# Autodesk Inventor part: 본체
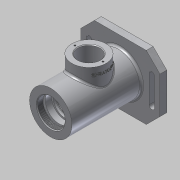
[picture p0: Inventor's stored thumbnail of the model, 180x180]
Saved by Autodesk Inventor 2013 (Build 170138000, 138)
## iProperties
Created: 2017-10
Part Number: 본체
Material: 알루미늄 6061
Document SubType Name: Modeling
Designer: Administrator
Density: 2.71 g/cm^3
Mass: 739.833 g
Surface Area: 655.925 cm^2
Volume: 273.001 cm^3
Author: Administrator
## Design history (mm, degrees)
sketch "스케치1"
  geometry: L1 (-58, 47)-(58, 47); L2 (58, 47)-(58, -47); L3 (58, -47)-(-58, -47); L4 (-58, -47)-(-58, 47); L5 (-58, 47)-(58, -47); L6 (58, 47)-(-58, -47); 1 further point
  constraints: 12 end point, 2 midpoint, 2 parallel, 1 horizontal, 1 perpendicular
  dimensions: "d3" = 116 distance of L2.end L3.end; "d4" = 94 distance of L1.end L2.end
extrude "돌출1" new body sketch "스케치1" distance "d5" = 10; taper "d6" = 0 deg
chamfer "모따기1" distance "d7" = 20; stored, may be unused: second distance "d8" = 2, angle "d9" = 45 deg
sketch "스케치2"
  geometry: L1 (31, 112)-(31, 10); L2 (27, 10)-(-27, 10) reference; L3 (0, 0)-(0, 188.497); L4 (-27, 0)-(27, 0) reference; L5 (47, 0)-(27, 0) reference; L6 (31, 112)-(21, 112); L7 (21, 112)-(21, 103); L8 (21, 103)-(24, 103); L9 (24, 103)-(24, 100); L10 (24, 100)-(20, 100); L11 (20, 100)-(20, 91); L12 (20, 91)-(17.5, 91); L13 (17.5, 91)-(17.5, 87.75); L14 (17.5, 87.75)-(18.5, 87.75); L15 (18.5, 87.75)-(18.5, 86); L16 (18.5, 86)-(17.5, 86); L17 (17.5, 86)-(17.5, 75); L18 (17.5, 75)-(26, 75); L19 (26, 75)-(26, 37); L20 (26, 37)-(17.5, 37); L21 (17.5, 37)-(17.5, 26.3); L22 (17.2, 26)-(16.5, 26); L23 (16.5, 26)-(16.5, 21); L24 (16.5, 21)-(10, 21); L25 (10, 21)-(10, 18.3); L26 (10, 18.3)-(12.2, 18.3); L27 (12.5, 18)-(12.5, 11.7); L28 (12.904, 11)-(16, 11); L29 (35, 0)-(35, -3); L30 (35, -3)-(0, -3); L31 (0, 0)-(0, -8.369); L32 (16, 11)-(22, -3); L33 (12.5, 11.7)-(12.904, 11); L34 (21, 112)-(0, 112); L35 (-47, 0)-(-47, 10) reference; L36 (-47, 10)-(47, 10) reference; L37 (47, 10)-(47, 0) reference; L38 (47, 0)-(-47, 0) reference; L39 (35, 0)-(31, 10); L40 (21, 103)-(0, 103); A1 r 0.3 centre (12.2, 18) between (12.5, 18) and (12.2, 18.3); A2 r 0.3 centre (17.2, 26.3) between (17.2, 26) and (17.5, 26.3)
  constraints: 66 end point, 23 parallel, 8 perpendicular, 6 point on line, 4 point on circle, 4 tangent, 2 centre point, 1 equal radius
  dimensions: "d10" = 62 diameter of L1 L3; "d14" = 42 diameter of L7 L3; "d15" = 48 diameter of L9 L3; "d16" = 40 diameter of L11 L3; "d17" = 35 diameter of L13 L3; "d18" = 37 diameter of L15 L3; "d19" = 35 diameter of L17 L3; "d20" = 52 diameter of L19 L3; "d21" = 35 diameter of L21 L3; "d22" = 33 diameter of L23 L3; "d23" = 20 diameter of L25 L3; "d24" = 25 diameter of L27 L3; "d25" = 32 diameter of L28.end L3; "d26" = 115 distance between parallel lines of L30 L6; "d27" = 44 diameter of L32.end L31; "d28" = 70 diameter of L29 L31; "d29" = 3 distance of L8.end L9.end; "d31" = 12 distance between parallel lines of L10 L6; "d32" = 21 distance between parallel lines of L12 L6; "d33" = 3 distance of L29.start L29.end; "d34" = 1.75 distance of L14.end L15.end; "d35" = 26 distance between parallel lines of L6 L16; "d36" = 11 distance of L16.end L17.end; "d37" = 38 distance of L18.end L19.end; "d38" = 14 distance between parallel lines of L30 L28; "d39" = 60 distance between parallel lines of L22 L16; "d40" = 5 distance of L22.end L23.end; "d42" = 2.7 distance of L24.end L25.end; "d43" = 30 deg angle of L27 L33; "d44" = 0.7 vertical distance of L28.start L27.end; "d45" = 0.3 radius of A1
  node "절단 모서리 투영1"
revolve "회전1" stored, may be unused: angle "d46" = 90 deg
revolve "회전2" stored, may be unused: angle "d47" = 90 deg
fillet "모깎기1" dims "d48" = 3
chamfer "모따기2" distance "d49" = 1; stored, may be unused: second distance "d50" = 2, angle "d51" = 45 deg
fillet "모깎기2" dims "d52" = 3
fillet "모깎기3" dims "d53" = 3
node "작업 평면1"
sketch "스케치3"
  geometry: L1 (38, 0)-(-38, 0) reference; L2 (-31, 112)-(31, 112) reference; C1 r 25 at (0, 56); 2 further points
  constraints: 1 centre point, 1 midpoint, 1 vertical alignment
  dimensions: "d55" = 56 distance from line of L2 C1.centre; "d56" = 50 diameter of C1
extrude "돌출2" join sketch "스케치3" stored distance "d57" = 10; taper "d58" = 0 deg
sketch "스케치4"
  geometry: C1 r 25 at (0, 0) reference; C2 r 16 at (0, 0); 1 further point
  constraints: 1 centre point, 1 coincident
  dimensions: "d59" = 32 diameter of C2
extrude "돌출3" cut sketch "스케치4" stored distance "d60" = 10; taper "d61" = 0 deg
chamfer "모따기4" distance "d65" = 1; stored, may be unused: second distance "d66" = 2, angle "d67" = 45 deg
fillet "모깎기4" dims "d68" = 3
sketch "스케치5"
  geometry: C1 r 25 at (0, 0) reference; C2 r 17 at (0, 0) reference; A1 r 20.5 centre (0, 0) between (-20.5, 0) and (20.5, 0); 1 further point
  constraints: 2 horizontal alignment, 2 point on circle, 1 centre point, 1 coincident
  dimensions: "d69" = 41 diameter of A1
hole "구멍1" sketch "스케치5" at (-20.5, 0), (20.5, 0) diameter "d70" = 2.459; stored, may be unused: countersink angle "d74" = 90 deg, drill point angle "d76" = 118 deg; dims "d71" = 6, "d72" = 4, "d73" = 2, "d75" = 8
sketch "스케치6"
  geometry: L1 (-42, 20)-(-42, -20); L2 (-50, 20)-(-50, -20); L3 (-38, 47)-(38, 47) reference; L4 (0, 0)-(0, 31); L5 (42, 20)-(42, -20); L6 (50, 20)-(50, -20); A1 r 4 centre (-46, 20) between (-42, 20) and (-50, 20); A2 r 4 centre (-46, -20) between (-50, -20) and (-42, -20); A3 r 4 centre (46, -20) between (42, -20) and (50, -20); A4 r 4 centre (46, 20) between (50, 20) and (42, 20)
  constraints: 10 end point, 8 point on circle, 6 symmetric about line, 4 centre point, 4 tangent, 1 equal radius, 1 perpendicular, 1 vertical, 1 vertical alignment, 3 other
  dimensions: "d79" = 46 horizontal distance of A2.centre L4.start; "d80" = 4 radius of A1; "d81" = 40 distance of A2.centre A1.centre; "d82" = 20 vertical distance of L4.start A1.centre
extrude "돌출4" cut sketch "스케치6" stored distance "d83" = 10; taper "d84" = 0 deg
node "작업 평면2"
sketch "스케치7"
  geometry: L1 (-78, 56)-(-16, 56) reference; L2 (0, 25)-(0, -25) reference; 2 further points
  constraints: 1 other
  dimensions: "d85" = 56 distance from line of L1 point (-10, 0); "d86" = 10 distance from line of L2 point (-10, 0)
feature "엠보싱1" sketch "스케치7" dims "d3" = 116, "d4" = 94, "d87" = 0.5, "d88" = 0
sketch "스케치8"
  geometry: C1 r 31 at (0, 0) reference; 1 further point
  constraints: 1 coincident
hole "구멍2" sketch "스케치8" at (0, 0) diameter "d89" = 40.376; stored, may be unused: countersink angle "d93" = 90 deg, drill point angle "d95" = 0 deg; dims "d90" = 6, "d91" = 4, "d92" = 2, "d94" = 9
fillet "모깎기5" dims "d96" = 3
chamfer "모따기5" distance "d97" = 1; stored, may be unused: second distance "d98" = 2, angle "d99" = 45 deg
node "솔리드1"
other parameters: "d54" = 47
